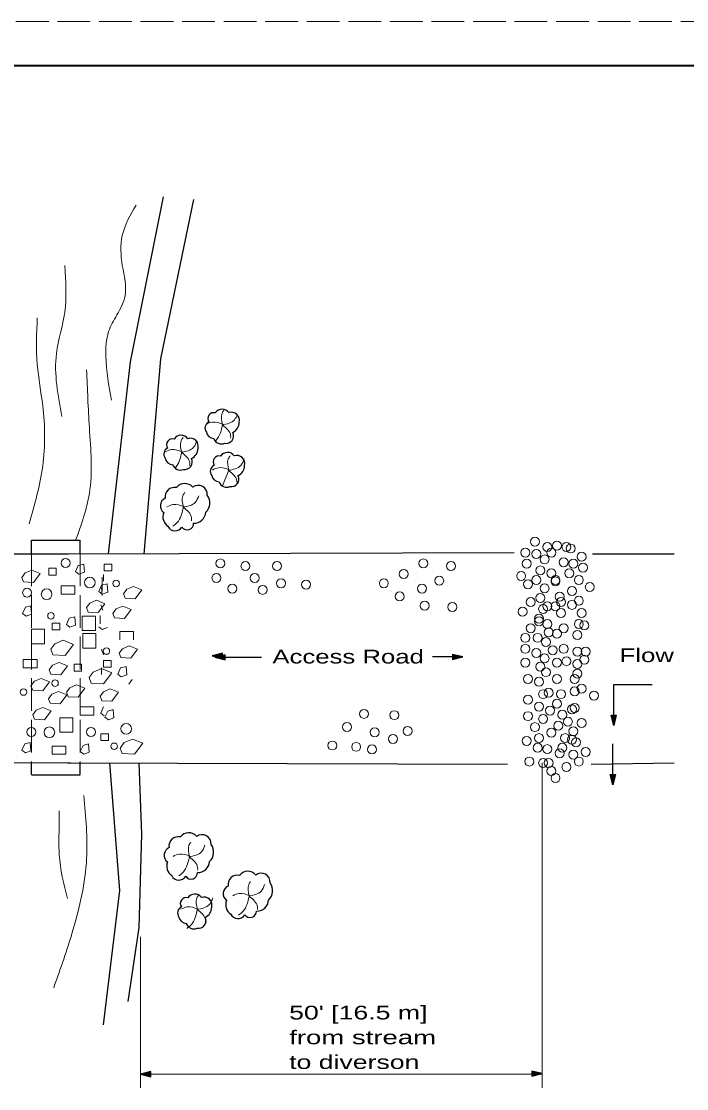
# Model space of a CAD drawing. Extents: x 1083.1 to 1117.1, y 719.4 to 741.4.
# Drawn here: x 1096.52 to 1104.08, y 729.24 to 741.35 of the extents above; entities that cross this region are included whole.
import ezdxf

# ---------------------------------------------------------------- set-up
doc = ezdxf.new("R2010")
doc.units = 0
doc.header["$LTSCALE"] = 0.062
doc.linetypes.add('LONG_DASHED', pattern=[7.5, 6, -1.5])
doc.layers.add('1', color=7, linetype='Continuous', lineweight=13)

msp = doc.modelspace()

# ---------------------------------------------------------------- hatches: boundary and pattern name
at = {"layer": '1'}
for points in [[(1098.805, 734.17917), (1098.6875, 734.14983), (1098.805, 734.1205)], [(1098.83617, 734.16367), (1098.71867, 734.13425), (1098.83617, 734.10483)], [(1101.41808, 734.10867), (1101.53558, 734.138), (1101.41808, 734.16733)], [(1103.27775, 733.4755), (1103.24833, 733.358), (1103.21892, 733.4755)], [(1103.26758, 732.80525), (1103.23817, 732.68775), (1103.20875, 732.80525)], [(1097.98975, 729.42983), (1097.87225, 729.4005), (1097.98975, 729.37117)], [(1102.31967, 729.37817), (1102.43717, 729.40758), (1102.31967, 729.437)]]:
    msp.add_hatch(color=256, dxfattribs=at).paths.add_polyline_path(points)

# ---------------------------------------------------------------- linework, layer by layer
at = {"layer": '1', "lineweight": 25}
for p, q in [((1085.12642, 740.85408), (1116.62642, 740.85408)), ((1096.63592, 735.46467), (1097.18733, 735.46467)), ((1096.63592, 735.31258), (1096.63592, 735.46467)), ((1097.18733, 735.31258), (1097.18733, 735.46467)), ((1090.24975, 735.32317), (1097.05567, 735.3075)), ((1097.04483, 735.3075), (1102.11867, 735.32317)), ((1103.00767, 735.3075), (1103.93383, 735.3075)), ((1098.71867, 734.13425), (1099.24892, 734.13425)), ((1101.53558, 734.138), (1101.19042, 734.138)), ((1090.42133, 732.95158), (1097.07958, 732.93758)), ((1096.63592, 732.8025), (1096.63592, 732.94233)), ((1097.04483, 732.93767), (1102.04075, 732.92042)), ((1097.18733, 732.8025), (1097.18733, 732.94233)), ((1102.99208, 732.92042), (1103.93383, 732.93767)), ((1096.63592, 732.79808), (1097.18733, 732.79808))]:
    msp.add_line(p, q, dxfattribs=at)
at = {"layer": '1', "lineweight": 40}
msp.add_line((1085.12642, 740.85408), (1116.62642, 740.85408), dxfattribs=at)
at = {"layer": '1'}
for p, q in [((1098.8765, 736.26017), (1098.80442, 736.08142)), ((1097.43733, 734.88125), (1097.43733, 735.045)), ((1097.45425, 735.07475), (1097.45425, 734.99675)), ((1097.43775, 734.83442), (1097.43, 734.928)), ((1097.42308, 734.73158), (1097.4465, 734.66925)), ((1097.41433, 734.60825), (1097.41433, 734.51467)), ((1097.63925, 734.33283), (1097.63925, 734.42642)), ((1097.43, 734.22617), (1097.45342, 734.16383)), ((1097.42958, 733.93767), (1097.42958, 734.01567)), ((1097.77667, 733.88125), (1097.7385, 733.83033)), ((1102.43717, 732.93767), (1102.43717, 729.2445)), ((1096.63592, 732.8025), (1096.63592, 732.82025)), ((1097.18733, 732.8025), (1097.18733, 732.82025)), ((1097.87225, 730.95908), (1097.87225, 729.2445)), ((1097.87225, 729.4005), (1102.43717, 729.4005))]:
    msp.add_line(p, q, dxfattribs=at)
at = {"layer": '1', "linetype": 'LONG_DASHED'}
for p, q in [((1096.63592, 735.31258), (1096.63592, 732.94233)), ((1097.18733, 735.31258), (1097.18733, 732.94233))]:
    msp.add_line(p, q, dxfattribs=at)
msp.add_lwpolyline([(1083.12642, 719.35408), (1117.12642, 719.35408), (1117.12642, 741.35408), (1083.12642, 741.35408)], close=True, dxfattribs=at)
at = {"layer": '1', "lineweight": 40}
msp.add_lwpolyline([(1116.62642, 719.85408), (1085.12642, 719.85408), (1085.12642, 740.85408), (1116.62642, 740.85408)], dxfattribs=at)
at = {"layer": '1', "lineweight": 25}
for points in [[(1097.51, 735.3075), (1097.75992, 737.49017), (1098.13408, 739.36108)], [(1097.91583, 735.30658), (1098.10292, 737.52133), (1098.47708, 739.32992)], [(1103.24833, 733.358), (1103.24833, 733.82517), (1103.68483, 733.82517)], [(1103.23817, 732.68775), (1103.23817, 732.901), (1103.23817, 733.151)], [(1097.52075, 732.93767), (1097.63525, 731.48758), (1097.44817, 729.95967)], [(1097.85342, 732.93767), (1097.88458, 732.12692), (1097.85342, 731.06675), (1097.72867, 730.22483)]]:
    msp.add_lwpolyline(points, dxfattribs=at)
at = {"layer": '1'}
for points in [[(1097.2275, 735.19317), (1097.16508, 735.17758), (1097.13392, 735.10742), (1097.17292, 735.07625), (1097.23525, 735.09958)], [(1097.46133, 735.19317), (1097.54708, 735.19317), (1097.54708, 735.11517), (1097.46133, 735.11517)], [(1096.63967, 735.12417), (1096.56358, 735.09242), (1096.52542, 735.0415), (1096.5445, 734.99067), (1096.65867, 734.98433), (1096.73483, 735.08592)], [(1096.82992, 735.14642), (1096.91567, 735.14642), (1096.91567, 735.06842), (1096.82992, 735.06842)], [(1096.97025, 734.94358), (1097.12617, 734.94358), (1097.12617, 734.85), (1096.97025, 734.85)], [(1097.49258, 734.967), (1097.43017, 734.95142), (1097.399, 734.88125), (1097.438, 734.85008), (1097.50033, 734.87342)], [(1097.79442, 734.93758), (1097.71833, 734.90583), (1097.68017, 734.85492), (1097.69925, 734.80408), (1097.81342, 734.79775), (1097.88958, 734.89933)], [(1096.62725, 734.71742), (1096.56483, 734.70183), (1096.53367, 734.63167), (1096.57267, 734.6005), (1096.635, 734.62383)], [(1097.37242, 734.781), (1097.29633, 734.74925), (1097.25817, 734.69833), (1097.27725, 734.6475), (1097.39142, 734.64117), (1097.46758, 734.74275)], [(1097.67125, 734.71575), (1097.59517, 734.684), (1097.557, 734.63308), (1097.57608, 734.58225), (1097.69025, 734.57592), (1097.76642, 734.6775)], [(1097.12617, 734.59267), (1097.06375, 734.57708), (1097.03258, 734.50692), (1097.07158, 734.47575), (1097.13392, 734.49908)], [(1097.21192, 734.6005), (1097.36008, 734.6005), (1097.36008, 734.43675), (1097.21192, 734.43675)], [(1096.63508, 734.45233), (1096.78325, 734.45233), (1096.78325, 734.28858), (1096.63508, 734.28858)], [(1096.86892, 734.5225), (1096.95467, 734.5225), (1096.95467, 734.4445), (1096.86892, 734.4445)], [(1096.99367, 734.32758), (1096.90017, 734.28858), (1096.85333, 734.22617), (1096.87675, 734.16383), (1097.01708, 734.156), (1097.11058, 734.28075)], [(1097.21833, 734.403), (1097.3665, 734.403), (1097.3665, 734.23925), (1097.21833, 734.23925)], [(1097.74517, 734.26383), (1097.66908, 734.23208), (1097.63092, 734.18117), (1097.65, 734.13033), (1097.76417, 734.124), (1097.84033, 734.22558)], [(1096.5415, 734.10917), (1096.69742, 734.10917), (1096.69742, 734.01558), (1096.5415, 734.01558)], [(1096.94842, 734.07483), (1096.87233, 734.04308), (1096.83417, 733.99217), (1096.85325, 733.94133), (1096.96742, 733.935), (1097.04358, 734.03658)], [(1097.45217, 734.09892), (1097.53792, 734.09892), (1097.53792, 734.02092), (1097.45217, 734.02092)], [(1097.11842, 734.05467), (1097.20417, 734.05467), (1097.20417, 733.97667), (1097.11842, 733.97667)], [(1097.42875, 734.00525), (1097.33525, 733.96625), (1097.28842, 733.90383), (1097.31183, 733.8415), (1097.45217, 733.83367), (1097.54567, 733.95842)], [(1097.70942, 734.02867), (1097.647, 734.01308), (1097.61583, 733.94292), (1097.65483, 733.91175), (1097.71717, 733.93508)], [(1096.74308, 733.89408), (1096.667, 733.86233), (1096.62883, 733.81142), (1096.64792, 733.76058), (1096.76208, 733.75425), (1096.83825, 733.85583)], [(1097.1455, 733.82017), (1097.06942, 733.78842), (1097.03125, 733.7375), (1097.05033, 733.68667), (1097.1645, 733.68033), (1097.24067, 733.78192)], [(1096.94017, 733.74617), (1096.86408, 733.71442), (1096.82592, 733.6635), (1096.845, 733.61267), (1096.95917, 733.60633), (1097.03533, 733.70792)], [(1097.52833, 733.77508), (1097.45225, 733.74333), (1097.41408, 733.69242), (1097.43317, 733.64158), (1097.54733, 733.63525), (1097.6235, 733.73683)], [(1096.76433, 733.5645), (1096.68825, 733.53275), (1096.65008, 733.48183), (1096.66917, 733.431), (1096.78333, 733.42467), (1096.8595, 733.52625)], [(1097.1885, 733.57108), (1097.34442, 733.57108), (1097.34442, 733.4775), (1097.1885, 733.4775)], [(1097.56275, 733.53992), (1097.50033, 733.52433), (1097.46917, 733.45417), (1097.50817, 733.423), (1097.5705, 733.44633)], [(1096.95467, 733.44633), (1097.10283, 733.44633), (1097.10283, 733.28258), (1096.95467, 733.28258)], [(1097.42242, 733.267), (1097.50817, 733.267), (1097.50817, 733.189), (1097.42242, 733.189)], [(1096.6195, 733.16558), (1096.55708, 733.15), (1096.52592, 733.07983), (1096.56492, 733.04867), (1096.62725, 733.072)], [(1096.86883, 733.12658), (1097.02475, 733.12658), (1097.02475, 733.033), (1096.86883, 733.033)], [(1097.28208, 733.15), (1097.21967, 733.13442), (1097.1885, 733.06425), (1097.2275, 733.03308), (1097.28983, 733.05642)], [(1097.781, 733.20458), (1097.6875, 733.16558), (1097.64067, 733.10317), (1097.66408, 733.04083), (1097.80442, 733.033), (1097.89792, 733.15775)]]:
    msp.add_lwpolyline(points, close=True, dxfattribs=at)
for points in [[(1097.39758, 734.481), (1097.43658, 734.44983), (1097.49892, 734.47317)], [(1097.63925, 734.42642), (1097.79517, 734.42642), (1097.79517, 734.33283)], [(1097.45292, 733.57108), (1097.42175, 733.50092), (1097.46075, 733.46975)]]:
    msp.add_lwpolyline(points, dxfattribs=at)
at = {"layer": '1', "lineweight": 25}
for points in [[(1098.805, 734.17917), (1098.6875, 734.14983), (1098.805, 734.1205)], [(1098.83617, 734.16367), (1098.71867, 734.13425), (1098.83617, 734.10483)], [(1101.41808, 734.10867), (1101.53558, 734.138), (1101.41808, 734.16733)], [(1103.27775, 733.4755), (1103.24833, 733.358), (1103.21892, 733.4755)], [(1103.26758, 732.80525), (1103.23817, 732.68775), (1103.20875, 732.80525)], [(1097.98975, 729.42983), (1097.87225, 729.4005), (1097.98975, 729.37117)], [(1102.31967, 729.37817), (1102.43717, 729.40758), (1102.31967, 729.437)]]:
    msp.add_lwpolyline(points, close=True, dxfattribs=at)
at = {"layer": '1'}
for centre, radius in [((1102.35326, 735.44728), 0.05102), ((1102.4936, 735.38487), 0.05102), ((1102.60285, 735.40053), 0.05102), ((1102.71201, 735.38487), 0.05102), ((1102.75881, 735.36932), 0.05102), ((1102.2441, 735.32245), 0.05102), ((1102.36885, 735.30687), 0.05102), ((1102.46247, 735.24449), 0.05102), ((1102.54047, 735.32249), 0.05102), ((1102.88356, 735.27566), 0.05102), ((1097.02158, 735.20386), 0.05102), ((1098.78094, 735.19926), 0.05102), ((1099.06536, 735.16935), 0.05102), ((1099.42461, 735.16935), 0.05102), ((1101.08636, 735.19926), 0.05102), ((1101.40069, 735.16935), 0.05102), ((1102.25968, 735.1977), 0.05102), ((1102.41564, 735.11966), 0.05102), ((1102.68081, 735.21332), 0.05102), ((1102.78997, 735.19766), 0.05102), ((1102.89914, 735.15091), 0.05102), ((1097.29772, 734.98258), 0.06088), ((1098.73602, 735.03451), 0.05102), ((1099.17019, 735.03451), 0.05102), ((1100.86177, 735.07943), 0.05102), ((1101.26594, 735.0046), 0.05102), ((1102.19726, 735.05728), 0.05102), ((1102.36885, 735.01045), 0.05102), ((1102.54047, 735.08849), 0.05102), ((1102.58722, 735.01049), 0.05102), ((1102.58722, 734.99482), 0.05102), ((1102.74322, 735.08849), 0.05102), ((1102.85239, 735.01049), 0.05102), ((1102.85239, 735.01049), 0.05102), ((1096.58508, 734.86853), 0.05102), ((1096.80655, 734.85), 0.06088), ((1097.59604, 734.97178), 0.03705), ((1098.91569, 734.91476), 0.05102), ((1099.25994, 734.89976), 0.05102), ((1099.46952, 734.97468), 0.05102), ((1099.75402, 734.95968), 0.05102), ((1100.63719, 734.97468), 0.05102), ((1101.07136, 734.91476), 0.05102), ((1102.27526, 734.96362), 0.05102), ((1102.46247, 734.91682), 0.05102), ((1102.77439, 734.88566), 0.05102), ((1102.9771, 734.93245), 0.05102), ((1100.81686, 734.82485), 0.05102), ((1102.30651, 734.76078), 0.05102), ((1102.41564, 734.80766), 0.05102), ((1102.63406, 734.82324), 0.05102), ((1102.64964, 734.76082), 0.05102), ((1102.85239, 734.77641), 0.05102), ((1101.10127, 734.7201), 0.05102), ((1101.41569, 734.7051), 0.05102), ((1102.21293, 734.65162), 0.05102), ((1102.44689, 734.68282), 0.05102), ((1102.49364, 734.71399), 0.05102), ((1102.58722, 734.71399), 0.05102), ((1102.64964, 734.63599), 0.05102), ((1102.77439, 734.72966), 0.05102), ((1102.88356, 734.63599), 0.05102), ((1096.85545, 734.60528), 0.03705), ((1102.40001, 734.57353), 0.05102), ((1102.40006, 734.54241), 0.05102), ((1102.49364, 734.51116), 0.05102), ((1102.85239, 734.51116), 0.05102), ((1102.91476, 734.49553), 0.05102), ((1102.30647, 734.46441), 0.05102), ((1102.50922, 734.41757), 0.05102), ((1102.60281, 734.40199), 0.05102), ((1102.68081, 734.46441), 0.05102), ((1102.83681, 734.38641), 0.05102), ((1102.2441, 734.35512), 0.05102), ((1102.38443, 734.35512), 0.05102), ((1102.47806, 734.30832), 0.05102), ((1097.48545, 734.20503), 0.03705), ((1102.2441, 734.23028), 0.05102), ((1102.36889, 734.18357), 0.05102), ((1102.55606, 734.21474), 0.05102), ((1102.68081, 734.23032), 0.05102), ((1102.83681, 734.19916), 0.05102), ((1102.93035, 734.19912), 0.05102), ((1102.2441, 734.07428), 0.05102), ((1102.41564, 734.02749), 0.05102), ((1102.46247, 734.12116), 0.05102), ((1102.60281, 734.07432), 0.05102), ((1102.71197, 734.08991), 0.05102), ((1102.83681, 734.05874), 0.05102), ((1102.91476, 734.10553), 0.05102), ((1102.27526, 733.88712), 0.05102), ((1102.47806, 733.96507), 0.05102), ((1102.60281, 733.88707), 0.05102), ((1102.80556, 733.88707), 0.05102), ((1102.83681, 733.94949), 0.05102), ((1096.9022, 733.84103), 0.03705), ((1102.40006, 733.85591), 0.05102), ((1102.88351, 733.77787), 0.05102), ((1096.54363, 733.73967), 0.03705), ((1102.27526, 733.65303), 0.05102), ((1102.44689, 733.71549), 0.05102), ((1102.50922, 733.73107), 0.05102), ((1102.64964, 733.71549), 0.05102), ((1102.80556, 733.74666), 0.05102), ((1103.02393, 733.69987), 0.05102), ((1102.40006, 733.57507), 0.05102), ((1102.52481, 733.52824), 0.05102), ((1102.60281, 733.60624), 0.05102), ((1102.77439, 733.54382), 0.05102), ((1102.80556, 733.55949), 0.05102), ((1100.41269, 733.4921), 0.05102), ((1100.75694, 733.4771), 0.05102), ((1102.27526, 733.46578), 0.05102), ((1102.44689, 733.43466), 0.05102), ((1102.66522, 733.48141), 0.05102), ((1102.72764, 733.40341), 0.05102), ((1096.63183, 733.28545), 0.05102), ((1096.8378, 733.28258), 0.06088), ((1097.31008, 733.28545), 0.05102), ((1097.71088, 733.32158), 0.06088), ((1100.21802, 733.34226), 0.05102), ((1100.53244, 733.28243), 0.05102), ((1100.90669, 733.29735), 0.05102), ((1102.35331, 733.34099), 0.05102), ((1102.61839, 733.35666), 0.05102), ((1102.78997, 733.29424), 0.05102), ((1102.88351, 733.38778), 0.05102), ((1100.74202, 733.20751), 0.05102), ((1102.25968, 733.18495), 0.05102), ((1102.40006, 733.21624), 0.05102), ((1102.54047, 733.27857), 0.05102), ((1102.69639, 733.21624), 0.05102), ((1102.77439, 733.20057), 0.05102), ((1102.82114, 733.16941), 0.05102), ((1097.57262, 733.12361), 0.03705), ((1100.05336, 733.13268), 0.05102), ((1100.32286, 733.11768), 0.05102), ((1100.50252, 733.08768), 0.05102), ((1102.38447, 733.10699), 0.05102), ((1102.49364, 733.09141), 0.05102), ((1102.63406, 733.04457), 0.05102), ((1102.66522, 733.10699), 0.05102), ((1102.93035, 733.06012), 0.05102), ((1102.29089, 732.95099), 0.05102), ((1102.44689, 732.93532), 0.05102), ((1102.50922, 732.93532), 0.05102), ((1102.78997, 733.02899), 0.05102), ((1102.85239, 732.95099), 0.05102), ((1102.54047, 732.84174), 0.05102), ((1102.71197, 732.88857), 0.05102), ((1102.58722, 732.76374), 0.05102)]:
    msp.add_circle(centre, radius, dxfattribs=at)
at = {"layer": '1', "lineweight": 25}
for centre, radius, start, end in [((1098.70388, 736.84466), 0.06676, 73.45349, 214.76336), ((1098.80151, 736.85692), 0.09411, 35.96461, 146.65194), ((1098.90642, 736.82644), 0.09044, 345.02203, 108.53509), ((1098.68274, 736.73697), 0.07735, 115.82411, 216.94314), ((1098.86595, 736.80283), 0.12784, 294.97991, 0.10653), ((1098.23622, 736.54833), 0.06676, 73.45349, 214.76336), ((1098.33384, 736.56059), 0.09411, 35.96461, 146.65194), ((1098.43876, 736.5301), 0.09044, 345.02203, 108.53509), ((1098.71311, 736.71058), 0.09436, 192.30376, 265.25213), ((1098.79191, 736.64857), 0.09234, 200.28911, 293.28837), ((1098.84393, 736.64782), 0.08549, 259.54267, 27.23416), ((1098.21507, 736.44063), 0.07735, 115.82411, 216.94314), ((1098.39829, 736.50649), 0.12784, 294.97991, 0.10653), ((1098.24544, 736.41425), 0.09436, 192.30376, 265.25213), ((1098.37626, 736.35149), 0.08549, 259.54267, 27.23416), ((1098.7643, 736.35341), 0.06676, 73.45349, 214.76336), ((1098.86192, 736.36567), 0.09411, 35.96461, 146.65194), ((1098.96684, 736.33519), 0.09044, 345.02203, 108.53509), ((1098.32424, 736.35223), 0.09234, 200.28911, 293.28837), ((1098.74315, 736.24572), 0.07735, 115.82411, 216.94314), ((1098.92637, 736.31158), 0.12784, 294.97991, 0.10653), ((1098.77352, 736.21933), 0.09436, 192.30376, 265.25213), ((1098.85232, 736.15732), 0.09234, 200.28911, 293.28837), ((1098.90435, 736.15657), 0.08549, 259.54267, 27.23416), ((1098.25877, 735.95663), 0.10621, 76.91487, 189.15854), ((1098.37686, 735.99097), 0.11671, 38.98642, 143.69126), ((1098.52994, 735.98441), 0.10143, 354.15853, 127.94053), ((1098.19332, 735.853), 0.09526, 114.43796, 233.55409), ((1098.51705, 735.88673), 0.14345, 312.33225, 37.51454), ((1098.2547, 735.72775), 0.12759, 157.59992, 236.32816), ((1098.48274, 735.78692), 0.13107, 267.14672, 357.27472), ((1098.40342, 735.65366), 0.07283, 213.92462, 1.85124), ((1098.2658, 735.66055), 0.09066, 205.4749, 328.37444), ((1098.42043, 732.02552), 0.11671, 38.98642, 143.69126), ((1098.5735, 732.01895), 0.10143, 354.15853, 127.94053), ((1098.30233, 731.99117), 0.10621, 76.91487, 189.15854), ((1098.56062, 731.92127), 0.14345, 312.33225, 37.51454), ((1098.23689, 731.88754), 0.09526, 114.43796, 233.55409), ((1098.29826, 731.76229), 0.12759, 157.59992, 236.32816), ((1098.5263, 731.82146), 0.13107, 267.14672, 357.27472), ((1098.30936, 731.6951), 0.09066, 205.4749, 328.37444), ((1098.44699, 731.6882), 0.07283, 213.92462, 1.85124), ((1098.97275, 731.55442), 0.10621, 76.91487, 189.15854), ((1099.09084, 731.58877), 0.11671, 38.98642, 143.69126), ((1099.24392, 731.5822), 0.10143, 354.15853, 127.94053), ((1098.90731, 731.45079), 0.09526, 114.43796, 233.55409), ((1099.23104, 731.48452), 0.14345, 312.33225, 37.51454), ((1098.39205, 731.339), 0.06676, 73.45349, 214.76336), ((1098.48967, 731.35126), 0.09411, 35.96461, 146.65194), ((1098.59459, 731.32077), 0.09044, 345.02203, 108.53509), ((1098.3709, 731.2313), 0.07735, 115.82411, 216.94314), ((1098.55412, 731.29716), 0.12784, 294.97991, 0.10653), ((1098.96868, 731.32554), 0.12759, 157.59992, 236.32816), ((1099.19672, 731.38471), 0.13107, 267.14672, 357.27472), ((1098.40127, 731.20492), 0.09436, 192.30376, 265.25213), ((1098.5321, 731.14215), 0.08549, 259.54267, 27.23416), ((1098.97978, 731.25835), 0.09066, 205.4749, 328.37444), ((1099.1174, 731.25145), 0.07283, 213.92462, 1.85124), ((1098.48007, 731.1429), 0.09234, 200.28911, 293.28837)]:
    msp.add_arc(centre, radius, start, end, dxfattribs=at)
at = {"layer": '1'}
for points in [[(1097.82225, 739.26758), (1097.66633, 738.92458), (1097.66633, 738.58158), (1097.69758, 738.23858), (1097.604, 738.02025), (1097.51042, 737.83317), (1097.47925, 737.55258), (1097.54167, 737.05367)], [(1096.98033, 736.86658), (1096.918, 737.58375), (1097.01158, 738.05142), (1097.01158, 738.58158)], [(1096.60617, 735.6505), (1096.76208, 736.30525), (1096.76208, 736.99125), (1096.69975, 737.459), (1096.69975, 737.98908)], [(1097.13625, 735.46342), (1097.29217, 735.9935), (1097.29217, 736.74183), (1097.261, 737.39667)], [(1098.80525, 736.77575), (1098.79867, 736.90442), (1098.82058, 736.94125)], [(1098.79867, 736.773), (1098.94083, 736.83083), (1098.97225, 736.88842)], [(1098.81258, 736.77867), (1098.68925, 736.80458), (1098.61817, 736.77825)], [(1098.80508, 736.77833), (1098.733, 736.59958), (1098.72183, 736.58842)], [(1098.80408, 736.773), (1098.89708, 736.65217), (1098.89708, 736.62058)], [(1098.34083, 736.46308), (1098.33425, 736.59175), (1098.35617, 736.62858)], [(1098.34817, 736.466), (1098.22483, 736.49192), (1098.15375, 736.46558)], [(1098.33425, 736.46033), (1098.47642, 736.51817), (1098.51475, 736.59175)], [(1098.34067, 736.46567), (1098.26858, 736.28692), (1098.26408, 736.28217)], [(1098.33967, 736.46033), (1098.43267, 736.3395), (1098.43267, 736.30792)], [(1098.87667, 736.25758), (1098.87008, 736.38625), (1098.892, 736.42308)], [(1098.87008, 736.25483), (1099.01225, 736.31267), (1099.05058, 736.38625)], [(1098.884, 736.2605), (1098.76067, 736.28642), (1098.68958, 736.26008)], [(1098.8755, 736.25483), (1098.9685, 736.134), (1098.9685, 736.10242)], [(1098.36058, 735.83925), (1098.354, 735.96792), (1098.37592, 736.00475)], [(1098.354, 735.8365), (1098.49617, 735.89433), (1098.5345, 735.96792)], [(1098.36792, 735.84217), (1098.24458, 735.86808), (1098.1735, 735.84175)], [(1098.36042, 735.84183), (1098.28833, 735.66308), (1098.23917, 735.62108)], [(1098.35942, 735.8365), (1098.45242, 735.71567), (1098.45242, 735.68408)], [(1097.22983, 732.5635), (1097.261, 731.84633), (1097.10508, 731.03558), (1096.88683, 730.38075)], [(1097.04275, 731.39408), (1096.94925, 731.89292), (1096.94925, 732.23592), (1096.94925, 732.39183)], [(1098.43017, 731.87142), (1098.42358, 732.00008), (1098.4455, 732.03692)], [(1098.42358, 731.86867), (1098.56575, 731.9265), (1098.60408, 732.00008)], [(1098.4375, 731.87433), (1098.31417, 731.90025), (1098.24308, 731.87392)], [(1098.43, 731.874), (1098.35792, 731.69525), (1098.30875, 731.65325)], [(1098.429, 731.86867), (1098.522, 731.74783), (1098.522, 731.71625)], [(1099.10892, 731.42475), (1099.10233, 731.55342), (1099.12425, 731.59025)], [(1099.10233, 731.422), (1099.2445, 731.47983), (1099.28283, 731.55342)], [(1098.5195, 731.27283), (1098.51292, 731.4015), (1098.53483, 731.43833)], [(1098.51292, 731.27008), (1098.65508, 731.32792), (1098.69342, 731.4015)], [(1099.11625, 731.42767), (1098.99292, 731.45358), (1098.92183, 731.42725)], [(1099.10875, 731.42733), (1099.03667, 731.24858), (1098.9875, 731.20658)], [(1099.10775, 731.422), (1099.20075, 731.30117), (1099.20075, 731.26958)], [(1098.52683, 731.27575), (1098.4035, 731.30167), (1098.33242, 731.27533)], [(1098.51933, 731.27542), (1098.44725, 731.09667), (1098.39808, 731.05467)], [(1098.51833, 731.27008), (1098.61133, 731.14925), (1098.61133, 731.11767)]]:
    msp.add_spline(points, degree=3, dxfattribs=at)

# ---------------------------------------------------------------- texts
for s, width, p in [('Access Road', 1.4, (1099.37125, 734.06383)), ('Flow', 1.4, (1103.31567, 734.0795)), ("50' [16.5 m]", 1.45, (1099.56142, 730.0225)), ('from stream', 1.5, (1099.56142, 729.7415)), ('to diverson', 1.45, (1099.56142, 729.4605))]:
    msp.add_text(s, height=0.156, dxfattribs=dict(at, width=width)).set_placement(p)

doc.saveas('drawing.dxf')
